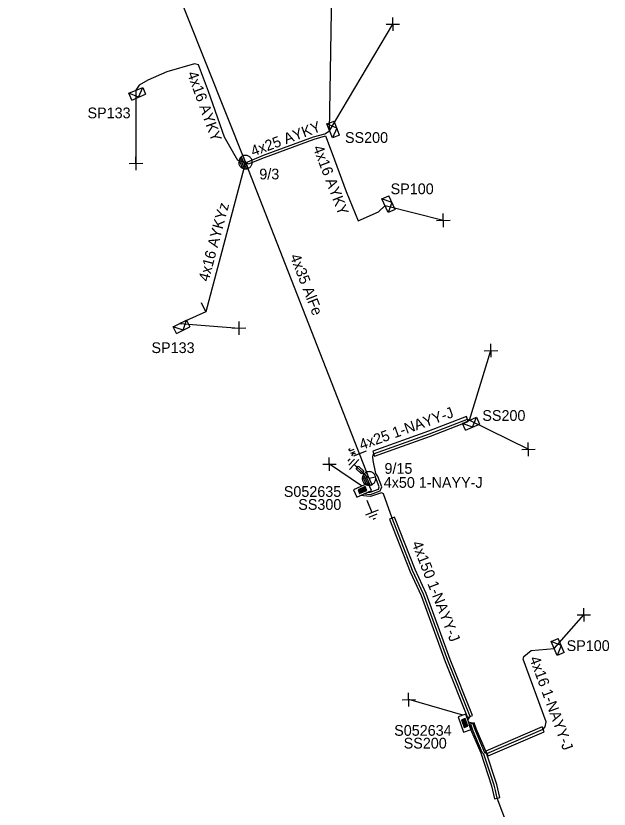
# Model space of a CAD drawing. Extents: x -762504 to -761250, y -1152974 to -1152253.
# Drawn here: x -761519.3 to -761464.3, y -1152464.4 to -1152391 of the extents above; entities that cross this region are included whole.
import ezdxf

# ---------------------------------------------------------------- set-up
doc = ezdxf.new("R2010")
doc.units = 0
for name, color, linetype in [('Vrstva 1', 7, 'Continuous'), ('Vrstva 12', 7, 'Continuous'), ('Vrstva 13', 7, 'Continuous'), ('Vrstva 15', 7, 'Continuous'), ('Vrstva 16', 7, 'Continuous'), ('Vrstva 18', 7, 'Continuous'), ('Vrstva 2', 7, 'Continuous'), ('Vrstva 20', 7, 'Continuous'), ('Vrstva 28', 7, 'Continuous'), ('Vrstva 29', 7, 'Continuous'), ('Vrstva 30', 7, 'Continuous'), ('Vrstva 31', 7, 'Continuous'), ('Vrstva 33', 7, 'Continuous'), ('Vrstva 34', 7, 'Continuous'), ('Vrstva 5', 7, 'Continuous'), ('Vrstva 52', 7, 'Continuous'), ('Vrstva 54', 7, 'Continuous'), ('Vrstva 55', 7, 'Continuous'), ('Vrstva 59', 7, 'Continuous'), ('Vrstva 6', 7, 'Continuous')]:
    doc.layers.add(name, color=color, linetype=linetype)

msp = doc.modelspace()

# ---------------------------------------------------------------- linework, layer by layer
at = {"layer": 'Vrstva 1'}
msp.add_lwpolyline([(-761486.59, -1152433.8), (-761498.04, -1152404.51), (-761508.91, -1152377.22), (-761518.58, -1152351.93), (-761519.32, -1152341.37)], dxfattribs=at)
at = {"layer": 'Vrstva 13'}
for points in [[(-761497.807, -1152405.097), (-761497.748, -1152405.069), (-761497.691, -1152405.035), (-761497.638, -1152404.995), (-761497.59, -1152404.95), (-761497.547, -1152404.9), (-761497.509, -1152404.846), (-761497.477, -1152404.789), (-761497.451, -1152404.728), (-761497.432, -1152404.665), (-761497.419, -1152404.6), (-761497.414, -1152404.535), (-761497.415, -1152404.469), (-761497.423, -1152404.403), (-761497.438, -1152404.339), (-761497.459, -1152404.277), (-761497.487, -1152404.217), (-761497.521, -1152404.16), (-761497.561, -1152404.108), (-761497.606, -1152404.059), (-761497.655, -1152404.016), (-761497.71, -1152403.978), (-761497.767, -1152403.946), (-761497.828, -1152403.921), (-761497.891, -1152403.901), (-761497.956, -1152403.889), (-761498.021, -1152403.883), (-761498.087, -1152403.884), (-761498.153, -1152403.892), (-761498.217, -1152403.907), (-761498.279, -1152403.928), (-761498.339, -1152403.956), (-761498.396, -1152403.99), (-761498.448, -1152404.03), (-761498.497, -1152404.075), (-761498.54, -1152404.125), (-761498.578, -1152404.179), (-761498.61, -1152404.236), (-761498.635, -1152404.297), (-761498.655, -1152404.36), (-761498.667, -1152404.425), (-761498.673, -1152404.491), (-761498.672, -1152404.556), (-761498.664, -1152404.622), (-761498.649, -1152404.686), (-761498.627, -1152404.748), (-761498.6, -1152404.808), (-761498.566, -1152404.865), (-761498.526, -1152404.917), (-761498.481, -1152404.966), (-761498.431, -1152405.009), (-761498.377, -1152405.047), (-761498.319, -1152405.079), (-761498.259, -1152405.104), (-761498.196, -1152405.124), (-761498.131, -1152405.136), (-761498.065, -1152405.142), (-761498, -1152405.141), (-761497.934, -1152405.133), (-761497.87, -1152405.118), (-761497.807, -1152405.097)], [(-761498.276, -1152403.925), (-761497.804, -1152405.093)], [(-761498.618, -1152404.34), (-761498.346, -1152405.015)], [(-761498.533, -1152404.156), (-761498.153, -1152405.096)], [(-761498.429, -1152404.019), (-761497.991, -1152405.105)], [(-761501.73, -1152418.378), (-761502.126, -1152417.528)], [(-761486.338, -1152434.378), (-761486.279, -1152434.348), (-761486.224, -1152434.312), (-761486.172, -1152434.27), (-761486.126, -1152434.224), (-761486.084, -1152434.173), (-761486.048, -1152434.117), (-761486.018, -1152434.059), (-761485.995, -1152433.997), (-761485.978, -1152433.934), (-761485.967, -1152433.868), (-761485.964, -1152433.802), (-761485.967, -1152433.737), (-761485.978, -1152433.671), (-761485.995, -1152433.608), (-761486.018, -1152433.546), (-761486.048, -1152433.488), (-761486.084, -1152433.432), (-761486.126, -1152433.381), (-761486.172, -1152433.334), (-761486.223, -1152433.293), (-761486.279, -1152433.257), (-761486.338, -1152433.227), (-761486.399, -1152433.203), (-761486.463, -1152433.186), (-761486.528, -1152433.176), (-761486.594, -1152433.173), (-761486.66, -1152433.176), (-761486.725, -1152433.186), (-761486.788, -1152433.203), (-761486.85, -1152433.227), (-761486.909, -1152433.257), (-761486.964, -1152433.293), (-761487.015, -1152433.334), (-761487.062, -1152433.381), (-761487.103, -1152433.432), (-761487.139, -1152433.487), (-761487.169, -1152433.546), (-761487.193, -1152433.608), (-761487.21, -1152433.671), (-761487.22, -1152433.737), (-761487.224, -1152433.803), (-761487.22, -1152433.868), (-761487.21, -1152433.933), (-761487.193, -1152433.997), (-761487.169, -1152434.059), (-761487.139, -1152434.117), (-761487.103, -1152434.173), (-761487.062, -1152434.224), (-761487.015, -1152434.271), (-761486.964, -1152434.312), (-761486.909, -1152434.348), (-761486.85, -1152434.378), (-761486.788, -1152434.401), (-761486.725, -1152434.418), (-761486.66, -1152434.429), (-761486.594, -1152434.432), (-761486.528, -1152434.429), (-761486.463, -1152434.418), (-761486.399, -1152434.402), (-761486.338, -1152434.378)], [(-761486.847, -1152433.224), (-761486.335, -1152434.374)], [(-761487.175, -1152433.65), (-761486.878, -1152434.315)], [(-761487.096, -1152433.464), (-761486.683, -1152434.39)], [(-761486.997, -1152433.323), (-761486.52, -1152434.393)]]:
    msp.add_lwpolyline(points, dxfattribs=at)
at = {"layer": 'Vrstva 15'}
for points in [[(-761488.523, -1152432.186), (-761488.432, -1152432.088)], [(-761488.464, -1152432.584), (-761487.926, -1152432.008)], [(-761488.432, -1152432.088), (-761488.345, -1152431.995)], [(-761488.401, -1152432.972), (-761487.549, -1152432.058)], [(-761487.061, -1152433.367), (-761487.975, -1152432.515)], [(-761486.806, -1152435.811), (-761486.338, -1152436.97)], [(-761485.758, -1152436.736), (-761486.917, -1152437.205)], [(-761485.865, -1152437.114), (-761486.596, -1152437.409)], [(-761486.103, -1152437.55), (-761486.222, -1152437.598)], [(-761485.98, -1152437.5), (-761486.103, -1152437.55)]]:
    msp.add_lwpolyline(points, dxfattribs=at)
at = {"layer": 'Vrstva 16'}
for points in [[(-761487.665, -1152432.794), (-761487.956, -1152432.523)], [(-761487.779, -1152432.917), (-761487.554, -1152432.676)], [(-761487.297, -1152433.367), (-761487.779, -1152432.917)], [(-761487.554, -1152432.676), (-761487.072, -1152433.125)], [(-761486.585, -1152433.801), (-761487.355, -1152433.083)], [(-761487.355, -1152433.083), (-761487.225, -1152433.124)], [(-761487.355, -1152433.083), (-761487.306, -1152433.21)], [(-761487.072, -1152433.125), (-761487.297, -1152433.367)]]:
    msp.add_lwpolyline(points, dxfattribs=at)
at = {"layer": 'Vrstva 18'}
for points in [[(-761488.426, -1152431.18), (-761488.422, -1152431.099)], [(-761488.422, -1152431.099), (-761488.377, -1152431.065)], [(-761488.377, -1152431.065), (-761488.332, -1152431.046)], [(-761488.415, -1152431.207), (-761488.426, -1152431.18)], [(-761488.357, -1152431.258), (-761488.415, -1152431.207)], [(-761488.3, -1152431.256), (-761488.357, -1152431.258)], [(-761487.921, -1152431.326), (-761488.305, -1152431.481)], [(-761487.999, -1152431.135), (-761488.3, -1152431.256)], [(-761488.055, -1152431.455), (-761488.214, -1152431.705)], [(-761488.159, -1152431.422), (-761487.844, -1152431.518)], [(-761486.865, -1152431.26), (-761488.024, -1152431.729)]]:
    msp.add_lwpolyline(points, dxfattribs=at)
at = {"layer": 'Vrstva 20'}
for points in [[(-761486.25, -1152431.27), (-761486.08, -1152431.74), (-761480.91, -1152429.89), (-761477.39, -1152428.53), (-761477.56, -1152428.06), (-761481.09, -1152429.43)], [(-761477.46, -1152455.93), (-761477, -1152455.75), (-761479.07, -1152450.57), (-761481.31, -1152444.44), (-761482.32, -1152442.24), (-761484.22, -1152437.39), (-761484.68, -1152437.57), (-761482.78, -1152442.44), (-761481.77, -1152444.63), (-761479.53, -1152450.76)], [(-761474.97, -1152463.46), (-761474.48, -1152463.35), (-761474.74, -1152462.14), (-761475.78, -1152459.04), (-761476.63, -1152457.06), (-761476.85, -1152456.42), (-761477.33, -1152456.58), (-761477.09, -1152457.24), (-761476.24, -1152459.22), (-761475.23, -1152462.25)], [(-761475.56, -1152459.5), (-761470.36, -1152457.25), (-761470.56, -1152456.79), (-761475.76, -1152459.04)]]:
    msp.add_lwpolyline(points, close=True, dxfattribs=at)
at = {"layer": 'Vrstva 28'}
for points in [[(-761486.671, -1152434.234), (-761488.041, -1152434.844)], [(-761486.934, -1152434.558), (-761487.613, -1152434.86)], [(-761486.958, -1152434.62), (-761487.551, -1152434.884)], [(-761486.982, -1152434.682), (-761487.489, -1152434.908)], [(-761487.006, -1152434.745), (-761487.426, -1152434.932)], [(-761486.967, -1152434.831), (-761487.006, -1152434.745)], [(-761486.905, -1152434.855), (-761486.982, -1152434.682)], [(-761486.842, -1152434.879), (-761486.958, -1152434.62)], [(-761486.78, -1152434.903), (-761486.934, -1152434.558)], [(-761486.366, -1152434.919), (-761486.671, -1152434.234)], [(-761488.041, -1152434.844), (-761487.736, -1152435.529)], [(-761487.736, -1152435.529), (-761486.366, -1152434.919)], [(-761487.613, -1152434.86), (-761487.46, -1152435.206)], [(-761487.551, -1152434.884), (-761487.436, -1152435.143)], [(-761487.489, -1152434.908), (-761487.412, -1152435.081)], [(-761487.46, -1152435.206), (-761486.78, -1152434.903)], [(-761487.436, -1152435.143), (-761486.842, -1152434.879)], [(-761487.426, -1152434.932), (-761487.388, -1152435.018)], [(-761487.412, -1152435.081), (-761486.905, -1152434.855)], [(-761487.388, -1152435.018), (-761486.967, -1152434.831)], [(-761487.024, -1152434.805), (-761487.369, -1152434.958)], [(-761477.633, -1152455.626), (-761478.337, -1152455.883)], [(-761478.337, -1152455.883), (-761477.824, -1152457.292)], [(-761477.677, -1152456.038), (-761478.033, -1152456.168)], [(-761477.423, -1152456.738), (-761477.677, -1152456.038)], [(-761477.12, -1152457.036), (-761477.633, -1152455.626)], [(-761478.033, -1152456.168), (-761477.778, -1152456.867)], [(-761477.706, -1152456.099), (-761477.972, -1152456.196)], [(-761477.972, -1152456.196), (-761477.75, -1152456.806)], [(-761477.734, -1152456.16), (-761477.912, -1152456.224)], [(-761477.912, -1152456.224), (-761477.722, -1152456.746)], [(-761477.762, -1152456.22), (-761477.851, -1152456.252)], [(-761477.851, -1152456.252), (-761477.693, -1152456.685)], [(-761477.792, -1152456.275), (-761477.663, -1152456.63)], [(-761477.778, -1152456.867), (-761477.423, -1152456.738)], [(-761477.605, -1152456.653), (-761477.762, -1152456.22)], [(-761477.75, -1152456.806), (-761477.484, -1152456.709)], [(-761477.544, -1152456.681), (-761477.734, -1152456.16)], [(-761477.722, -1152456.746), (-761477.544, -1152456.681)], [(-761477.484, -1152456.709), (-761477.706, -1152456.099)], [(-761477.693, -1152456.685), (-761477.605, -1152456.653)], [(-761477.824, -1152457.292), (-761477.12, -1152457.036)]]:
    msp.add_lwpolyline(points, dxfattribs=at)
at = {"layer": 'Vrstva 31'}
for points in [[(-761508.583, -1152398.779), (-761508.857, -1152398.135), (-761507.568, -1152397.588), (-761507.295, -1152398.232)], [(-761507.939, -1152398.506), (-761507.568, -1152397.588)], [(-761507.939, -1152398.506), (-761508.857, -1152398.135)], [(-761508.583, -1152398.779), (-761507.295, -1152398.232)], [(-761489.334, -1152402.015), (-761489.988, -1152402.266), (-761490.489, -1152400.959), (-761489.836, -1152400.708)], [(-761489.585, -1152401.362), (-761490.489, -1152400.959)], [(-761489.334, -1152402.015), (-761489.836, -1152400.708)], [(-761489.585, -1152401.362), (-761489.988, -1152402.266)], [(-761484.184, -1152408.897), (-761484.824, -1152409.182), (-761485.393, -1152407.903), (-761484.754, -1152407.618)], [(-761484.469, -1152408.258), (-761485.393, -1152407.903)], [(-761484.469, -1152408.258), (-761484.824, -1152409.182)], [(-761484.184, -1152408.897), (-761484.754, -1152407.618)], [(-761504.438, -1152420.393), (-761504.756, -1152419.769), (-761503.509, -1152419.134), (-761503.191, -1152419.758)], [(-761503.815, -1152420.075), (-761503.509, -1152419.134)], [(-761503.815, -1152420.075), (-761504.756, -1152419.769)], [(-761504.438, -1152420.393), (-761503.191, -1152419.758)], [(-761477.638, -1152429.346), (-761477.922, -1152428.707), (-761476.643, -1152428.137), (-761476.359, -1152428.777)], [(-761476.998, -1152429.061), (-761476.643, -1152428.137)], [(-761476.998, -1152429.061), (-761477.922, -1152428.707)], [(-761477.638, -1152429.346), (-761476.359, -1152428.777)], [(-761468.511, -1152449.923), (-761469.155, -1152450.197), (-761469.702, -1152448.908), (-761469.058, -1152448.634)], [(-761468.511, -1152449.923), (-761469.058, -1152448.634)], [(-761468.784, -1152449.279), (-761469.702, -1152448.908)], [(-761468.784, -1152449.279), (-761469.155, -1152450.197)]]:
    msp.add_lwpolyline(points, dxfattribs=at)
at = {"layer": 'Vrstva 34'}
for points in [[(-761484.369, -1152392.365), (-761484.391, -1152391.115)], [(-761485.005, -1152391.751), (-761483.755, -1152391.729)], [(-761508.815, -1152404.641), (-761507.565, -1152404.619)], [(-761508.179, -1152405.255), (-761508.201, -1152404.005)], [(-761479.699, -1152410.525), (-761479.721, -1152409.275)], [(-761480.335, -1152409.911), (-761479.085, -1152409.889)], [(-761498.619, -1152420.505), (-761498.641, -1152419.255)], [(-761499.255, -1152419.891), (-761498.005, -1152419.869)], [(-761475.279, -1152422.585), (-761475.301, -1152421.335)], [(-761475.915, -1152421.971), (-761474.665, -1152421.949)], [(-761472.445, -1152431.111), (-761471.195, -1152431.089)], [(-761471.809, -1152431.725), (-761471.831, -1152430.475)], [(-761490.885, -1152432.491), (-761489.635, -1152432.469)], [(-761490.249, -1152433.105), (-761490.271, -1152431.855)], [(-761467.305, -1152446.441), (-761466.055, -1152446.419)], [(-761466.669, -1152447.055), (-761466.691, -1152445.805)], [(-761482.899, -1152454.905), (-761482.921, -1152453.655)], [(-761483.535, -1152454.291), (-761482.285, -1152454.269)]]:
    msp.add_lwpolyline(points, dxfattribs=at)
at = {"layer": 'Vrstva 5'}
for points in [[(-761486.67, -1152435.06), (-761486.49, -1152435.08), (-761485.72, -1152434.8), (-761485.64, -1152434.59), (-761485.98, -1152433.69), (-761486.59, -1152433.8)], [(-761477.43, -1152456.19), (-761477.23, -1152455.84), (-761479.3, -1152450.66), (-761481.54, -1152444.53), (-761482.55, -1152442.34), (-761484.45, -1152437.48), (-761485.26, -1152435.22), (-761485.45, -1152435.12), (-761486.44, -1152435.48), (-761487.43, -1152435.38)], [(-761465.27, -1152489.98), (-761465.04, -1152489.69), (-761467.61, -1152482.65), (-761469.54, -1152477.18), (-761472.7, -1152468.73), (-761474.72, -1152463.41), (-761474.86, -1152462.7), (-761474.98, -1152462.21), (-761475.94, -1152459.34), (-761476.1, -1152459.17), (-761476.95, -1152457.19), (-761477.17, -1152456.57), (-761477.31, -1152456.52)]]:
    msp.add_lwpolyline(points, dxfattribs=at)
at = {"layer": 'Vrstva 52'}
for points in [[(-761498.04, -1152404.51), (-761498.76, -1152404.37), (-761499.97, -1152402.2), (-761501.46, -1152397.98), (-761502.39, -1152395.51), (-761502.76, -1152395.42), (-761505.34, -1152396.16), (-761507.08, -1152396.93), (-761507.89, -1152397.38), (-761508.21, -1152397.86)], [(-761498.04, -1152404.51), (-761497.82, -1152404.48), (-761496.36, -1152403.88), (-761491.75, -1152402.18), (-761490.69, -1152401.89), (-761490.24, -1152401.61)], [(-761498.04, -1152404.51), (-761497.75, -1152404.67), (-761496.29, -1152404.07), (-761491.69, -1152402.37), (-761490.62, -1152402.08), (-761490.02, -1152403.72), (-761488.72, -1152407.24), (-761487.6, -1152409.94), (-761485.7, -1152409.12), (-761485.11, -1152408.54)], [(-761487.05, -1152435.22), (-761486.46, -1152435.28), (-761485.57, -1152434.96), (-761485.42, -1152434.59), (-761485.79, -1152433.63), (-761485.96, -1152433.33), (-761486.22, -1152432.13), (-761486.24, -1152431.79), (-761486.17, -1152431.51), (-761481, -1152429.66), (-761477.48, -1152428.3), (-761477.28, -1152428.42)], [(-761477.38, -1152456.33), (-761477.01, -1152456.43), (-761476.77, -1152457.11), (-761475.88, -1152459.18), (-761475.66, -1152459.27), (-761470.46, -1152457.02), (-761470.26, -1152456.81), (-761470.19, -1152456.35), (-761472.32, -1152450.55), (-761472.25, -1152450.28), (-761471.56, -1152449.74), (-761469.43, -1152449.55)]]:
    msp.add_lwpolyline(points, dxfattribs=at)
at = {"layer": 'Vrstva 54'}
msp.add_lwpolyline([(-761498.04, -1152404.51), (-761501.73, -1152418.38), (-761504.13, -1152419.45)], dxfattribs=at)
at = {"layer": 'Vrstva 59'}
for points in [[(-761490.24, -1152401.61), (-761489.95, -1152383.14)], [(-761490.24, -1152401.61), (-761484.38, -1152391.74)], [(-761508.21, -1152397.86), (-761508.19, -1152404.63)], [(-761485.11, -1152408.54), (-761479.71, -1152409.9)], [(-761504.13, -1152419.45), (-761498.63, -1152419.88)], [(-761477.28, -1152428.42), (-761475.29, -1152421.96)], [(-761477.28, -1152428.42), (-761471.82, -1152431.1)], [(-761487.28, -1152434.5), (-761490.26, -1152432.48)], [(-761469.43, -1152449.55), (-761466.68, -1152446.43)], [(-761477.9, -1152455.72), (-761482.91, -1152454.28)]]:
    msp.add_lwpolyline(points, dxfattribs=at)

# ---------------------------------------------------------------- texts
at = {"layer": 'Vrstva 12'}
for s, p in [('9/3', (-761496.76, -1152406.11)), ('9/15', (-761485.16, -1152433.37))]:
    msp.add_text(s, height=0.9943, dxfattribs=at).set_placement(p)
at = {"layer": 'Vrstva 2'}
msp.add_text('4x35 AlFe', height=0.9943, rotation=291.20534, dxfattribs=at).set_placement((-761493.94, -1152413.23))
at = {"layer": 'Vrstva 29'}
for s, p in [('S052635', (-761494.49, -1152435.51)), ('S052634', (-761484.26, -1152457.63))]:
    msp.add_text(s, height=0.9943, dxfattribs=at).set_placement(p)
at = {"layer": 'Vrstva 30'}
for s, p in [('SS300', (-761493.15, -1152436.71)), ('SS200', (-761483.38, -1152458.81))]:
    msp.add_text(s, height=0.9943, dxfattribs=at).set_placement(p)
at = {"layer": 'Vrstva 33'}
for s, p in [('SP133', (-761512.68, -1152400.45)), ('SS200', (-761488.82, -1152402.73)), ('SP100', (-761484.59, -1152407.48)), ('SP133', (-761506.75, -1152422.19)), ('SS200', (-761476.09, -1152428.47)), ('SP100', (-761468.28, -1152449.78))]:
    msp.add_text(s, height=0.9943, dxfattribs=at).set_placement(p)
at = {"layer": 'Vrstva 54'}
for s, height, rotation, p in [('4x16 AYKY', 0.9943, 289.92813, (-761503.46, -1152396.3)), ('4x25 AYKY', 0.9943, 20.5221, (-761497.33, -1152404)), ('4x16 AYKY', 0.9943, 290.96843, (-761491.81, -1152403.17)), ('4x25 1-NAYY-J', 0.99429, 19.68892, (-761487.29, -1152431.18)), ('4x16 1-NAYY-J', 0.99428, 290.16532, (-761471.74, -1152450.47))]:
    msp.add_text(s, height=height, rotation=rotation, dxfattribs=at).set_placement(p)
at = {"layer": 'Vrstva 55'}
msp.add_text('4x16 AYKYz', height=0.9943, rotation=75.10131, dxfattribs=at).set_placement((-761501.46, -1152415.63))
at = {"layer": 'Vrstva 6'}
msp.add_text('4x50 1-NAYY-J', height=0.99429, dxfattribs=at).set_placement((-761485.23, -1152434.67))
msp.add_text('4x150 1-NAYY-J', height=0.99429, rotation=291.35284, dxfattribs=at).set_placement((-761482.65, -1152439.81))

doc.saveas('drawing.dxf')
